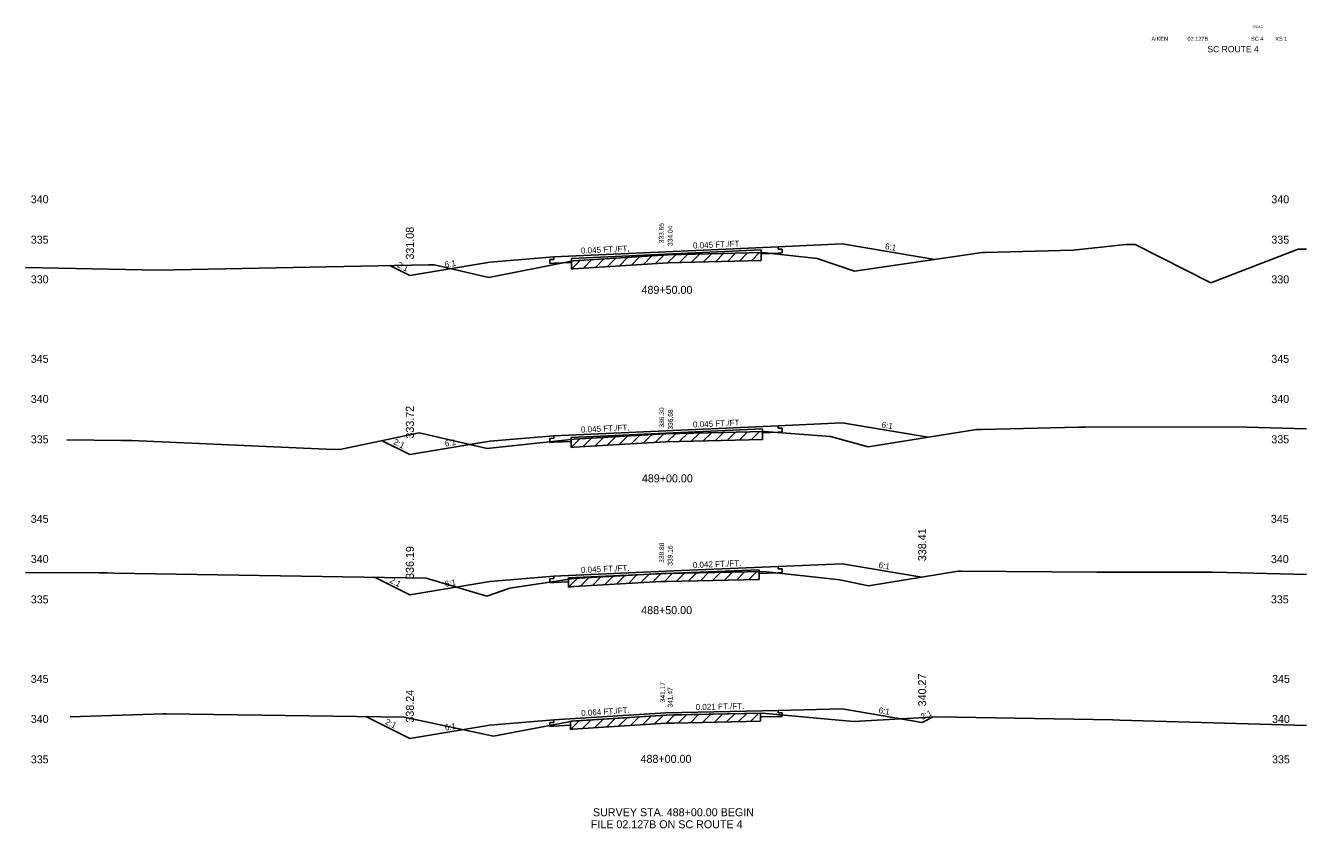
# Model space of a CAD drawing. Extents: x 883 to 1160, y 1002 to 4323.
# Drawn here: x 1000 to 1160, y 1002 to 1102.3 of the extents above; entities that cross this region are included whole.
import ezdxf

# ---------------------------------------------------------------- set-up
doc = ezdxf.new("R2010")
doc.units = 0
for name, color, linetype in [('Level 1', 7, 'Continuous'), ('Level 10', 7, 'Continuous'), ('Level 11', 7, 'Continuous'), ('Level 12', 7, 'Continuous'), ('Level 3', 7, 'Continuous'), ('Level 32', 7, 'Continuous'), ('Level 33', 7, 'Continuous'), ('Level 53', 7, 'Continuous'), ('Level 59', 7, 'Continuous'), ('Level 6', 7, 'Continuous'), ('Level 60', 7, 'Continuous'), ('Level 61', 7, 'Continuous'), ('Level 7', 7, 'Continuous')]:
    doc.layers.add(name, color=color, linetype=linetype)

msp = doc.modelspace()

# ---------------------------------------------------------------- linework, layer by layer
at = {"layer": 'Level 11'}
for p, q in [((1094, 1074.37), (1094, 1074.67)), ((1094.5, 1074.4), (1094, 1074.37)), ((1094, 1073.89), (1094.5, 1073.92)), ((1094.5, 1073.92), (1094.5, 1074.4)), ((1066, 1073.11), (1065.5, 1073.09)), ((1065.5, 1073.09), (1065.5, 1072.61)), ((1065.5, 1072.61), (1066, 1072.63)), ((1066, 1073.41), (1066, 1073.11)), ((1094, 1052.01), (1094, 1052.31)), ((1094.5, 1052.03), (1094, 1052.01)), ((1094, 1051.53), (1094.5, 1051.55)), ((1094.5, 1051.55), (1094.5, 1052.03)), ((1066, 1050.75), (1065.5, 1050.73)), ((1065.5, 1050.73), (1065.5, 1050.25)), ((1065.5, 1050.25), (1066, 1050.27)), ((1066, 1051.05), (1066, 1050.75)), ((1094, 1034.44), (1094, 1034.74)), ((1094.5, 1034.46), (1094, 1034.44)), ((1094, 1033.96), (1094.5, 1033.98)), ((1094.5, 1033.98), (1094.5, 1034.46)), ((1066, 1033.23), (1065.5, 1033.21)), ((1065.5, 1033.21), (1065.5, 1032.73)), ((1065.5, 1032.73), (1066, 1032.75)), ((1066, 1033.53), (1066, 1033.23)), ((1094, 1016.47), (1094, 1016.77)), ((1094.5, 1016.48), (1094, 1016.47)), ((1094.5, 1016), (1094.5, 1016.48)), ((1066, 1015.27), (1065.5, 1015.24)), ((1065.5, 1015.24), (1065.5, 1014.76)), ((1065.5, 1014.76), (1066, 1014.79)), ((1066, 1015.57), (1066, 1015.27)), ((1094, 1015.99), (1094.5, 1016))]:
    msp.add_line(p, q, dxfattribs=at)
at = {"layer": 'Level 12'}
for p, q in [((1091.9, 1073.95), (1091.9, 1073.8)), ((1091.9, 1073.8), (1094, 1073.89)), ((1068.18, 1072.73), (1066, 1072.63)), ((1068.18, 1072.88), (1068.18, 1072.73)), ((1092.07, 1051.6), (1092.07, 1051.45)), ((1092.07, 1051.45), (1094, 1051.53)), ((1068.14, 1050.37), (1066, 1050.27)), ((1068.14, 1050.62), (1068.14, 1050.37)), ((1091.64, 1034.1), (1091.64, 1033.86)), ((1091.64, 1033.86), (1094, 1033.96)), ((1067.8, 1032.83), (1066, 1032.75)), ((1067.8, 1033.14), (1067.8, 1032.83)), ((1091.8, 1016.42), (1091.8, 1015.94)), ((1068.06, 1014.92), (1066, 1014.79)), ((1068.06, 1015.37), (1068.06, 1014.92)), ((1091.8, 1015.94), (1094, 1015.99))]:
    msp.add_line(p, q, dxfattribs=at)
at = {"layer": 'Level 53'}
for p, q in [((1080, 1073.74), (1068.18, 1073.21)), ((1080, 1073.74), (1091.9, 1074.28)), ((1091.9, 1074.28), (1091.9, 1073.95)), ((1068.18, 1073.21), (1068.18, 1072.88)), ((1080, 1051.38), (1068.14, 1050.85)), ((1080, 1051.38), (1092.07, 1051.93)), ((1092.07, 1051.93), (1092.07, 1051.6)), ((1068.14, 1050.85), (1068.14, 1050.62)), ((1080, 1033.86), (1067.8, 1033.31)), ((1080, 1033.86), (1091.64, 1034.34)), ((1091.64, 1034.34), (1091.64, 1034.1)), ((1067.8, 1033.31), (1067.8, 1033.14)), ((1080, 1016.17), (1068.06, 1015.4)), ((1080, 1016.17), (1091.8, 1016.42)), ((1091.8, 1016.42), (1091.8, 1016.42)), ((1068.06, 1015.4), (1068.06, 1015.37))]:
    msp.add_line(p, q, dxfattribs=at)
at = {"layer": 'Level 59'}
for p, q in [((1066, 1073.41), (1080, 1074.04)), ((1080, 1074.04), (1094, 1074.67)), ((1066, 1051.05), (1080, 1051.68)), ((1080, 1051.68), (1094, 1052.31)), ((1066, 1033.53), (1080, 1034.16)), ((1080, 1034.16), (1094, 1034.74)), ((1066, 1015.57), (1080, 1016.47)), ((1080, 1016.47), (1094, 1016.77))]:
    msp.add_line(p, q, dxfattribs=at)
at = {"layer": 'Level 6'}
for p, q in [((1094, 1074.67), (1102, 1075.03)), ((1058, 1072.75), (1066, 1073.41)), ((1094, 1052.31), (1102, 1052.67)), ((1058, 1050.39), (1066, 1051.05)), ((1094, 1034.74), (1102, 1035.08)), ((1058, 1032.86), (1066, 1033.53)), ((1094, 1016.77), (1102, 1016.94)), ((1058, 1014.9), (1066, 1015.57))]:
    msp.add_line(p, q, dxfattribs=at)
at = {"layer": 'Level 60'}
for p, q in [((1068.41, 1072.93), (1080.29, 1073.67)), ((1080.29, 1073.67), (1092.06, 1073.96)), ((1092.06, 1073.96), (1098.88, 1073.21)), ((1103.53, 1071.62), (1119.5, 1073.97)), ((1119.5, 1073.97), (1119.88, 1073.98)), ((1119.88, 1073.98), (1130.88, 1074.27)), ((1130.88, 1074.27), (1137.46, 1074.96)), ((1137.46, 1074.96), (1138.63, 1074.96)), ((1138.63, 1074.96), (1148.06, 1070.18)), ((1148.06, 1070.18), (1158.99, 1074.39)), ((1158.99, 1074.39), (1160, 1074.36)), ((1000, 1072.07), (1014.57, 1071.79)), ((1016.48, 1071.76), (1050.35, 1072.42)), ((1050.35, 1072.42), (1051.02, 1072.42)), ((1051.02, 1072.42), (1057.88, 1070.83)), ((1057.88, 1070.83), (1068.41, 1072.93)), ((1098.88, 1073.21), (1103.53, 1071.62)), ((1014.57, 1071.79), (1016.48, 1071.76)), ((1039.46, 1049.38), (1049.17, 1051.44)), ((1049.17, 1051.44), (1057.66, 1049.49)), ((1076.98, 1051.13), (1080, 1051.3)), ((1080, 1051.3), (1092.26, 1051.61)), ((1092.26, 1051.61), (1100.56, 1050.99)), ((1105.24, 1049.67), (1118.81, 1051.87)), ((1118.81, 1051.87), (1119.51, 1051.86)), ((1119.51, 1051.86), (1131.54, 1052.15)), ((1131.54, 1052.15), (1132.39, 1052.15)), ((1132.39, 1052.15), (1151.14, 1052.2)), ((1151.14, 1052.2), (1154, 1052.12)), ((1154, 1052.12), (1160, 1051.93)), ((1005.15, 1050.56), (1011.95, 1050.48)), ((1011.95, 1050.48), (1013.27, 1050.46)), ((1013.27, 1050.46), (1038.46, 1049.36)), ((1057.66, 1049.49), (1068.54, 1050.66)), ((1068.54, 1050.66), (1076.98, 1051.13)), ((1100.56, 1050.99), (1105.24, 1049.67)), ((1038.46, 1049.36), (1039.46, 1049.38)), ((1000, 1034), (1009.19, 1033.94)), ((1009.19, 1033.94), (1010.17, 1033.93)), ((1010.17, 1033.93), (1011, 1033.89)), ((1011, 1033.89), (1050.05, 1033.3)), ((1068.49, 1033.25), (1079.41, 1033.85)), ((1079.41, 1033.85), (1080.05, 1033.88)), ((1080.05, 1033.88), (1092.22, 1034.11)), ((1092.22, 1034.11), (1101.71, 1033.07)), ((1105.31, 1032.33), (1116.48, 1034.17)), ((1116.48, 1034.17), (1116.92, 1034.16)), ((1116.92, 1034.16), (1133.84, 1034.04)), ((1133.84, 1034.04), (1148.22, 1034.05)), ((1148.22, 1034.05), (1150.1, 1034)), ((1150.1, 1034), (1160, 1033.73)), ((1050.05, 1033.3), (1057.63, 1031.04)), ((1057.63, 1031.04), (1060.51, 1032.02)), ((1060.51, 1032.02), (1068.49, 1033.25)), ((1101.71, 1033.07), (1105.31, 1032.33)), ((1005.55, 1015.94), (1017.22, 1016.32)), ((1017.22, 1016.32), (1017.55, 1016.32)), ((1017.55, 1016.32), (1047.3, 1015.92)), ((1068.32, 1015.41), (1080.04, 1016.17)), ((1080.04, 1016.17), (1080.96, 1016.19)), ((1080.96, 1016.19), (1092.01, 1016.42)), ((1092.01, 1016.42), (1103.44, 1015.36)), ((1047.3, 1015.92), (1058.43, 1013.56)), ((1058.43, 1013.56), (1068.32, 1015.41)), ((1103.44, 1015.36), (1113.84, 1015.98)), ((1113.84, 1015.98), (1135.82, 1015.57)), ((1135.82, 1015.57), (1136.7, 1015.53)), ((1136.7, 1015.53), (1160, 1014.87))]:
    msp.add_line(p, q, dxfattribs=at)
at = {"layer": 'Level 61'}
for p, q in [((1079.74, 1073.64), (1078.68, 1072.57)), ((1081.21, 1073.69), (1080.18, 1072.66)), ((1082.7, 1073.73), (1081.68, 1072.7)), ((1084.2, 1073.77), (1083.18, 1072.74)), ((1085.7, 1073.8), (1084.68, 1072.78)), ((1087.2, 1073.84), (1086.18, 1072.81)), ((1088.7, 1073.88), (1087.68, 1072.85)), ((1090.2, 1073.91), (1089.18, 1072.89)), ((1091.7, 1073.95), (1090.68, 1072.92)), ((1091.9, 1072.95), (1091.9, 1073.95)), ((1069.28, 1072.98), (1068.18, 1071.88)), ((1068.18, 1072.88), (1068.18, 1071.88)), ((1068.41, 1071.93), (1080.29, 1072.67)), ((1070.74, 1073.08), (1069.68, 1072.01)), ((1072.24, 1073.17), (1071.18, 1072.1)), ((1073.74, 1073.26), (1072.68, 1072.2)), ((1075.24, 1073.36), (1074.18, 1072.29)), ((1076.74, 1073.45), (1075.68, 1072.38)), ((1078.24, 1073.54), (1077.18, 1072.48)), ((1080.29, 1072.67), (1091.9, 1072.95)), ((1068.18, 1071.88), (1068.41, 1071.93)), ((1079.7, 1051.28), (1078.64, 1050.22)), ((1081.17, 1051.33), (1080.14, 1050.3)), ((1082.67, 1051.37), (1081.64, 1050.34)), ((1084.17, 1051.4), (1083.14, 1050.38)), ((1085.67, 1051.44), (1084.64, 1050.42)), ((1087.17, 1051.48), (1086.14, 1050.45)), ((1088.67, 1051.52), (1087.64, 1050.49)), ((1090.17, 1051.56), (1089.14, 1050.53)), ((1091.67, 1051.59), (1090.64, 1050.57)), ((1092.07, 1050.6), (1092.07, 1051.6)), ((1069.22, 1050.7), (1068.14, 1049.62)), ((1068.14, 1050.62), (1068.14, 1049.62)), ((1068.14, 1049.62), (1068.54, 1049.66)), ((1068.54, 1049.66), (1076.98, 1050.13)), ((1070.7, 1050.78), (1069.64, 1049.72)), ((1072.2, 1050.86), (1071.14, 1049.81)), ((1073.7, 1050.95), (1072.64, 1049.89)), ((1075.2, 1051.03), (1074.14, 1049.97)), ((1076.7, 1051.12), (1075.64, 1050.06)), ((1076.98, 1050.13), (1080, 1050.3)), ((1078.2, 1051.2), (1077.14, 1050.14)), ((1080, 1050.3), (1092.07, 1050.6)), ((1076.36, 1033.68), (1075.3, 1032.62)), ((1077.86, 1033.76), (1076.8, 1032.7)), ((1079.36, 1033.84), (1078.3, 1032.79)), ((1080.83, 1033.9), (1079.8, 1032.87)), ((1082.32, 1033.92), (1081.3, 1032.9)), ((1083.82, 1033.95), (1082.8, 1032.93)), ((1085.32, 1033.98), (1084.3, 1032.96)), ((1086.82, 1034.01), (1085.8, 1032.99)), ((1088.32, 1034.03), (1087.3, 1033.02)), ((1089.82, 1034.06), (1088.8, 1033.04)), ((1091.32, 1034.09), (1090.3, 1033.07)), ((1091.64, 1033.1), (1091.64, 1034.1)), ((1068.93, 1033.27), (1067.8, 1032.14)), ((1067.8, 1033.14), (1067.8, 1032.14)), ((1067.8, 1032.14), (1068.49, 1032.25)), ((1068.49, 1032.25), (1079.41, 1032.85)), ((1070.36, 1033.35), (1069.3, 1032.29)), ((1071.86, 1033.43), (1070.8, 1032.37)), ((1073.36, 1033.51), (1072.3, 1032.46)), ((1074.86, 1033.6), (1073.8, 1032.54)), ((1079.41, 1032.85), (1080.05, 1032.88)), ((1080.05, 1032.88), (1091.64, 1033.1)), ((1078.13, 1016.05), (1077.06, 1014.98)), ((1079.63, 1016.14), (1078.56, 1015.07)), ((1081.08, 1016.19), (1080.06, 1015.17)), ((1082.58, 1016.22), (1081.56, 1015.2)), ((1084.08, 1016.25), (1083.06, 1015.23)), ((1085.58, 1016.29), (1084.56, 1015.26)), ((1087.08, 1016.32), (1086.06, 1015.3)), ((1088.58, 1016.35), (1087.56, 1015.33)), ((1090.08, 1016.38), (1089.06, 1015.36)), ((1091.58, 1016.41), (1090.56, 1015.39)), ((1091.8, 1015.42), (1091.8, 1016.42)), ((1069.16, 1015.47), (1068.06, 1014.37)), ((1068.06, 1015.37), (1068.06, 1014.37)), ((1068.06, 1014.37), (1068.32, 1014.41)), ((1068.32, 1014.41), (1080.04, 1015.17)), ((1070.63, 1015.56), (1069.56, 1014.49)), ((1072.13, 1015.66), (1071.06, 1014.59)), ((1073.63, 1015.76), (1072.56, 1014.69)), ((1075.13, 1015.85), (1074.06, 1014.78)), ((1076.63, 1015.95), (1075.56, 1014.88)), ((1080.04, 1015.17), (1080.96, 1015.19)), ((1080.96, 1015.19), (1091.8, 1015.42))]:
    msp.add_line(p, q, dxfattribs=at)
at = {"layer": 'Level 7'}
for p, q in [((1102, 1075.03), (1113.6, 1073.1)), ((1045.5, 1072.33), (1048, 1071.08)), ((1048, 1071.08), (1058, 1072.75)), ((1102, 1052.67), (1112.74, 1050.88)), ((1044.53, 1050.45), (1048, 1048.72)), ((1048, 1048.72), (1058, 1050.39)), ((1102, 1035.08), (1111.94, 1033.42)), ((1043.59, 1033.4), (1048, 1031.19)), ((1048, 1031.19), (1058, 1032.86)), ((1102, 1016.94), (1112, 1015.27)), ((1042.5, 1015.99), (1048, 1013.24)), ((1048, 1013.24), (1058, 1014.9)), ((1112, 1015.27), (1113.37, 1015.95))]:
    msp.add_line(p, q, dxfattribs=at)

# ---------------------------------------------------------------- texts
at = {"layer": 'Level 1'}
for s, height, p in [('AIKEN', 0.5, (1140.64, 1100.41)), ('02.127B', 0.5, (1145.15, 1100.41)), ('SC 4', 0.5, (1153.09, 1100.41)), ('XS 1', 0.5, (1156.12, 1100.41)), ('SC ROUTE 4', 0.8, (1147.63, 1098.97)), ('489+50.00', 1, (1076.94, 1068.8)), ('489+00.00', 1, (1076.99, 1045.25)), ('488+50.00', 1, (1076.9, 1028.79)), ('488+00.00', 1, (1076.82, 1010.21)), ('SURVEY STA. 488+00.00 BEGIN', 1, (1070.88, 1003.54)), ('FILE 02.127B ON SC ROUTE 4 ', 1, (1070.61, 1002.04))]:
    msp.add_text(s, height=height, dxfattribs=at).set_placement(p)
at = {"layer": 'Level 10'}
for s, p in [('333.65', (1079.72, 1075.12)), ('336.30', (1079.76, 1052.08)), ('338.88', (1079.76, 1035.19)), ('341.17', (1079.88, 1017.77))]:
    msp.add_text(s, height=0.6, rotation=90, dxfattribs=at).set_placement(p)
at = {"layer": 'Level 3'}
for s, height, p in [('ROAD', 0.3, (1153.38, 1102)), (' 340', 1, (1000.27, 1080.11)), (' 340', 1, (1155.25, 1080.11)), (' 335', 1, (1000.27, 1075.07)), (' 335', 1, (1155.25, 1075.07)), (' 330', 1, (1000.27, 1070.11)), (' 330', 1, (1155.25, 1070.11)), (' 345', 1, (1000.27, 1060.18)), (' 345', 1, (1155.25, 1060.18)), (' 340', 1, (1000.27, 1055.17)), (' 340', 1, (1155.25, 1055.17)), (' 335', 1, (1000.27, 1050.13)), (' 335', 1, (1155.25, 1050.13)), (' 345', 1, (1000.27, 1040.19)), (' 345', 1, (1155.19, 1040.19)), (' 340', 1, (1000.27, 1035.17)), (' 340', 1, (1155.19, 1035.17)), (' 335', 1, (1000.27, 1030.13)), (' 335', 1, (1155.19, 1030.13)), (' 345', 1, (1000.27, 1020.2)), (' 345', 1, (1155.34, 1020.2)), (' 340', 1, (1000.27, 1015.19)), (' 340', 1, (1155.34, 1015.19)), (' 335', 1, (1000.27, 1010.15)), (' 335', 1, (1155.34, 1010.15))]:
    msp.add_text(s, height=height, dxfattribs=at).set_placement(p)
at = {"layer": 'Level 32'}
for s, rotation, p in [('0.045 FT./FT.', 2.5766, (1083.39, 1074.45)), ('0.045 FT./FT.', 2.5766, (1069.39, 1073.82)), ('6:1', 350.5377, (1107.32, 1074.4)), ('2:1', 333.435, (1046.35, 1072.18)), ('6:1', 9.4623, (1052.43, 1072.07)), ('0.045 FT./FT.', 2.5766, (1083.39, 1052.09)), ('6:1', 350.5377, (1106.89, 1052.11)), ('0.045 FT./FT.', 2.5766, (1069.39, 1051.46)), ('2:1', 333.435, (1045.87, 1050.06)), ('6:1', 9.4623, (1052.43, 1049.71)), ('0.042 FT./FT.', 2.3888, (1083.36, 1034.55)), ('6:1', 350.5377, (1106.52, 1034.58)), ('0.045 FT./FT.', 2.5766, (1069.39, 1033.93)), ('2:1', 333.435, (1045.4, 1032.77)), ('6:1', 9.4623, (1052.43, 1032.19)), ('0.021 FT./FT.', 1.2145, (1083.71, 1016.8)), ('0.064 FT./FT.', 3.6848, (1069.43, 1016.04)), ('6:1', 350.5377, (1106.52, 1016.44)), ('2:1', 26.5651, (1112.06, 1015.58)), ('2:1', 333.435, (1044.85, 1015.09)), ('6:1', 9.4623, (1052.43, 1014.23))]:
    msp.add_text(s, height=0.75, rotation=rotation, dxfattribs=at).set_placement(p)
at = {"layer": 'Level 33'}
for s, p in [('331.08', (1048.5, 1073.08)), ('333.72', (1048.5, 1050.72)), ('338.41', (1112.5, 1035.41)), ('336.19', (1048.5, 1033.19)), ('340.27', (1112.5, 1017.27)), ('338.24', (1048.5, 1015.24))]:
    msp.add_text(s, height=1, rotation=90, dxfattribs=at).set_placement(p)
at = {"layer": 'Level 59'}
for s, p in [(' 334.04', (1080.82, 1074.54)), (' 336.68', (1080.86, 1051.6)), (' 339.16', (1080.82, 1034.61)), (' 341.47', (1080.82, 1016.89))]:
    msp.add_text(s, height=0.6, rotation=90, dxfattribs=at).set_placement(p)

doc.saveas('drawing.dxf')
